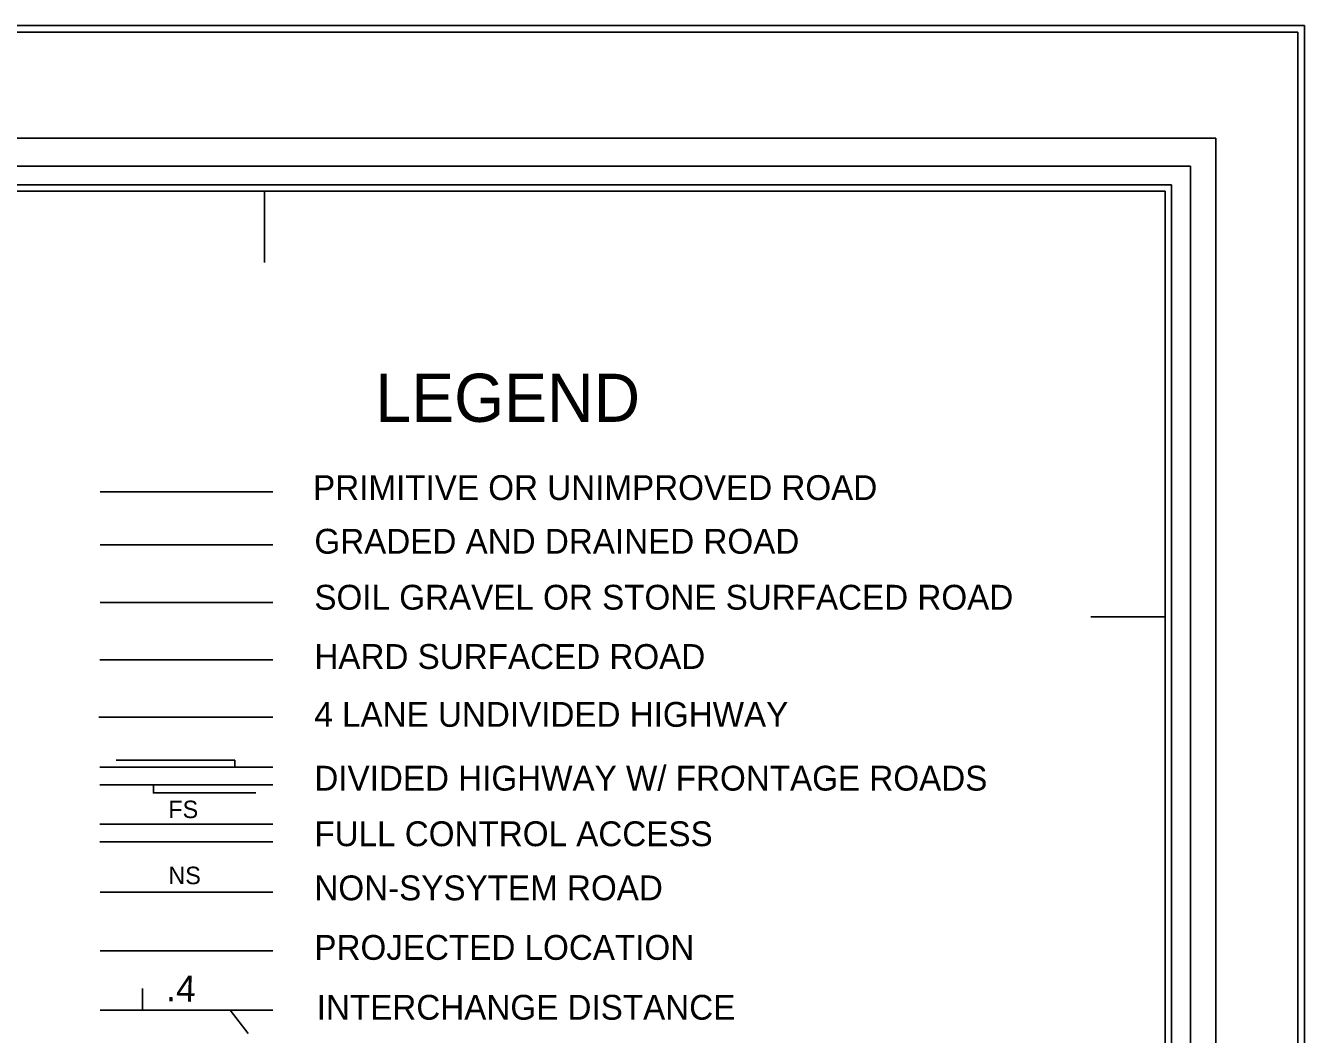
# Model space of a CAD drawing. Extents: x 5197761 to 5514561, y 1890130 to 2080942.
# Drawn here: x 5485322 to 5514561, y 2051880 to 2074930 of the extents above; entities that cross this region are included whole.
import ezdxf

# ---------------------------------------------------------------- set-up
doc = ezdxf.new("R2010")
doc.units = 0
for name, color, linetype in [('Exist Road Non-System Type 51', 7, 'Continuous'), ('Exist Road Non-System Type 51 Label', 7, 'Continuous'), ('Exist Road Primary Interstate Divided Center Attributed', 7, 'Continuous'), ('Exist Road Primary Interstate Label', 7, 'Continuous'), ('Exist Road Primary Interstate Service Attributed', 7, 'Continuous'), ('Exist Road Primary NC Attributed', 7, 'Continuous'), ('Exist Road Primary NC Label', 7, 'Continuous'), ('Exist Road Primary NC Service Mileage Hundredths English Label', 7, 'Continuous'), ('Exist Road Primary NC UnDivided 4 Lane Attributed', 7, 'Continuous'), ('Exist Road Primary NC UnDivided 4 Lane Label', 7, 'Continuous'), ('Exist Road Secondary Type 10 Attributed', 7, 'Continuous'), ('Exist Road Secondary Type 10 Label', 7, 'Continuous'), ('Exist Road Secondary Type 20 Attributed', 7, 'Continuous'), ('Exist Road Secondary Type 20 Label', 7, 'Continuous'), ('Exist Road Secondary Type 41 Attributed', 7, 'Continuous'), ('Exist Road Secondary Type 41 Label', 7, 'Continuous'), ('Exist Road Secondary Type 51 Attributed', 7, 'Continuous'), ('Exist Road Secondary Type 51 Label', 7, 'Continuous'), ('Map Preparation Base StatePlane Tick Mark', 7, 'Continuous'), ('Map Preparation Border Antique Large Shape', 7, 'Continuous'), ('Map Preparation Border Antique Small Shape', 7, 'Continuous'), ('Map Preparation Border Black Inside Shape', 7, 'Continuous'), ('Map Preparation Border Black Middle Shape', 7, 'Continuous'), ('Map Preparation Border Black Outside Shape', 7, 'Continuous'), ('Map Preparation County Base Legend CELL', 7, 'Continuous'), ('Prop Road Primary NC Projected', 7, 'Continuous'), ('Prop Road Primary NC Projected Label', 7, 'Continuous')]:
    doc.layers.add(name, color=color, linetype=linetype)

msp = doc.modelspace()

# ---------------------------------------------------------------- linework, layer by layer
at = {"layer": 'Exist Road Non-System Type 51'}
msp.add_line((5490973, 2055130), (5487024, 2055130), dxfattribs=at)
at = {"layer": 'Exist Road Primary Interstate Divided Center Attributed'}
for p, q in [((5490973, 2057984), (5487017, 2057984)), ((5490973, 2057584), (5487017, 2057584)), ((5490973, 2056681), (5487017, 2056681)), ((5490973, 2056281), (5487017, 2056281))]:
    msp.add_line(p, q, dxfattribs=at)
at = {"layer": 'Exist Road Primary Interstate Service Attributed'}
for points in [[(5490105, 2057989), (5490105, 2058144), (5487396, 2058144)], [(5488244, 2057587), (5488244, 2057396), (5490588, 2057396)]]:
    msp.add_lwpolyline(points, dxfattribs=at)
at = {"layer": 'Exist Road Primary NC Attributed'}
for p, q in [((5487993, 2052431), (5487993, 2052929)), ((5487993, 2052431), (5487026, 2052431)), ((5490000, 2052431), (5487993, 2052431)), ((5490973, 2052431), (5490000, 2052431)), ((5490000, 2052431), (5490410, 2051898))]:
    msp.add_line(p, q, dxfattribs=at)
at = {"layer": 'Exist Road Primary NC UnDivided 4 Lane Attributed'}
msp.add_line((5490973, 2059125), (5486999, 2059125), dxfattribs=at)
at = {"layer": 'Exist Road Secondary Type 10 Attributed'}
msp.add_line((5487024, 2064274), (5490973, 2064274), dxfattribs=at)
at = {"layer": 'Exist Road Secondary Type 20 Attributed'}
msp.add_line((5487024, 2063066), (5490973, 2063066), dxfattribs=at)
at = {"layer": 'Exist Road Secondary Type 41 Attributed'}
msp.add_line((5487024, 2061752), (5490973, 2061752), dxfattribs=at)
at = {"layer": 'Exist Road Secondary Type 51 Attributed'}
msp.add_line((5490973, 2060437), (5487017, 2060437), dxfattribs=at)
at = {"layer": 'Map Preparation Base StatePlane Tick Mark'}
for p, q in [((5490787, 2069519), (5490787, 2071145)), ((5509679, 2061420), (5511378, 2061420))]:
    msp.add_line(p, q, dxfattribs=at)
at = {"layer": 'Map Preparation Border Antique Large Shape'}
msp.add_lwpolyline([(5197907, 2074783), (5207205, 2074783), (5207205, 1892697), (5512539, 1892697), (5512539, 2072359), (5207205, 2072359), (5207205, 2074783), (5514414, 2074783), (5514414, 1890276), (5197907, 1890276)], close=True, dxfattribs=at)
at = {"layer": 'Map Preparation Border Antique Small Shape'}
msp.add_lwpolyline([(5207791, 2071720), (5208220, 2071720), (5208220, 1893712), (5511524, 1893712), (5511524, 2071291), (5208220, 2071291), (5208220, 2071720), (5207791, 2071720), (5511953, 2071720), (5511953, 1893283), (5208220, 1893283), (5207791, 1893283)], close=True, dxfattribs=at)
at = {"layer": 'Map Preparation Border Black Inside Shape'}
msp.add_lwpolyline([(5208220, 2071291), (5511524, 2071291), (5511524, 1893712), (5208366, 1893712), (5208366, 1893858), (5511378, 1893858), (5511378, 2071145), (5208366, 2071145), (5208366, 1893858), (5208366, 1893712), (5208220, 1893712), (5208220, 1893858)], close=True, dxfattribs=at)
at = {"layer": 'Map Preparation Border Black Middle Shape'}
msp.add_lwpolyline([(5207205, 2072359), (5512539, 2072359), (5512539, 1892697), (5511953, 1892697), (5207791, 1892697), (5207791, 1893283), (5511953, 1893283), (5511953, 2071720), (5207791, 2071720), (5207791, 1892697), (5207205, 1892697)], close=True, dxfattribs=at)
at = {"layer": 'Map Preparation Border Black Outside Shape'}
msp.add_lwpolyline([(5197761, 2074930), (5514561, 2074930), (5514561, 1890130), (5197907, 1890130), (5197907, 1890276), (5514414, 1890276), (5514414, 2074783), (5197907, 2074783), (5197907, 1890130), (5197761, 1890130)], close=True, dxfattribs=at)
at = {"layer": 'Prop Road Primary NC Projected'}
msp.add_line((5490973, 2053791), (5487024, 2053791), dxfattribs=at)

# ---------------------------------------------------------------- texts
at = {"layer": 'Exist Road Non-System Type 51 Label'}
for s, height, p in [('NS', 400, (5488586, 2055313)), ('NON-SYSYTEM ROAD', 567.41, (5491925, 2054945))]:
    msp.add_text(s, height=height, dxfattribs=at).set_placement(p)
at = {"layer": 'Exist Road Primary Interstate Label'}
for s, height, p in [('DIVIDED HIGHWAY W/ FRONTAGE ROADS', 567.41, (5491925, 2057451)), ('FS', 400, (5488586, 2056822)), ('FULL CONTROL ACCESS', 567.41, (5491925, 2056181))]:
    msp.add_text(s, height=height, dxfattribs=at).set_placement(p)
at = {"layer": 'Exist Road Primary NC Label'}
msp.add_text('INTERCHANGE DISTANCE', height=567.41, dxfattribs=at).set_placement((5491979, 2052216))
at = {"layer": 'Exist Road Primary NC Service Mileage Hundredths English Label'}
msp.add_text('.4', height=600, rotation=358.2237, dxfattribs=at).set_placement((5488534, 2052642))
at = {"layer": 'Exist Road Primary NC UnDivided 4 Lane Label'}
msp.add_text('4 LANE UNDIVIDED HIGHWAY', height=567.41, dxfattribs=at).set_placement((5491925, 2058908))
at = {"layer": 'Exist Road Secondary Type 10 Label'}
msp.add_text('PRIMITIVE OR UNIMPROVED ROAD', height=567.41, dxfattribs=at).set_placement((5491895, 2064090))
at = {"layer": 'Exist Road Secondary Type 20 Label'}
msp.add_text('GRADED AND DRAINED ROAD', height=567.41, dxfattribs=at).set_placement((5491925, 2062864))
at = {"layer": 'Exist Road Secondary Type 41 Label'}
msp.add_text('SOIL GRAVEL OR STONE SURFACED ROAD', height=567.41, dxfattribs=at).set_placement((5491925, 2061585))
at = {"layer": 'Exist Road Secondary Type 51 Label'}
msp.add_text('HARD SURFACED ROAD', height=567.41, dxfattribs=at).set_placement((5491925, 2060231))
at = {"layer": 'Map Preparation County Base Legend CELL'}
msp.add_text('LEGEND', height=1100, dxfattribs=at).set_placement((5493322, 2065876))
at = {"layer": 'Prop Road Primary NC Projected Label'}
msp.add_text('PROJECTED LOCATION', height=567.41, dxfattribs=at).set_placement((5491925, 2053584))

doc.saveas('drawing.dxf')
